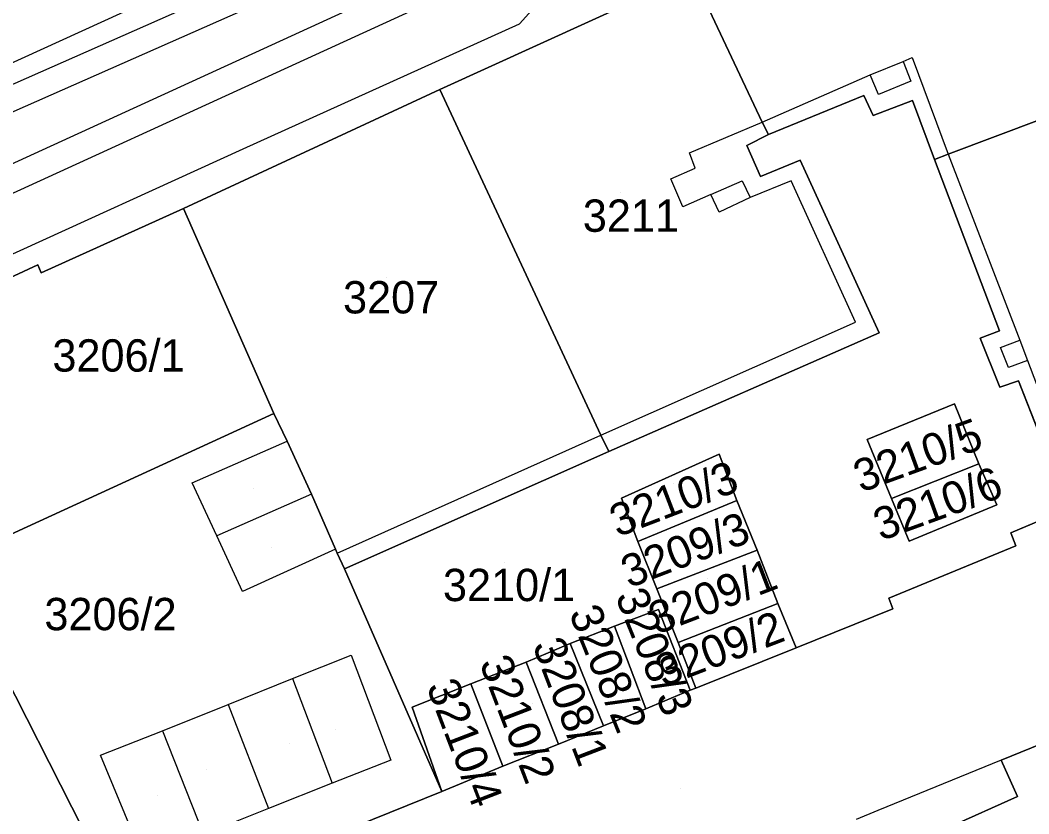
# Model space of a CAD drawing. Extents: x -264070 to -262271, y -1238894 to -1238141.
# Drawn here: x -262975.9 to -262913.5, y -1238614.4 to -1238565.3 of the extents above; entities that cross this region are included whole.
import ezdxf

# ---------------------------------------------------------------- set-up
doc = ezdxf.new("R2010")
doc.units = 0
for name, color, linetype in [('body_kn', 7, 'Continuous'), ('kladpar_druhypozemkov', 7, 'Continuous'), ('kladpar_hranice', 7, 'Continuous'), ('kladpar_parcelnecisla', 7, 'Continuous'), ('kladpar_plochy', 7, 'Continuous'), ('tarchy_linie', 7, 'Continuous'), ('zappar_hrandruhpozemk', 7, 'Continuous')]:
    doc.layers.add(name, color=color, linetype=linetype)

msp = doc.modelspace()

# ---------------------------------------------------------------- linework, layer by layer
at = {"layer": 'body_kn'}
for p, q in [((-262945.02, -1238565.56), (-262945.02, -1238565.56)), ((-262921.28, -1238567.88), (-262921.28, -1238567.88)), ((-262920.72, -1238567.63), (-262920.72, -1238567.63)), ((-262923.32, -1238568.71), (-262923.32, -1238568.71)), ((-262920.8, -1238569.09), (-262920.8, -1238569.09)), ((-262949.95, -1238569.62), (-262949.95, -1238569.62)), ((-262949.95, -1238569.62), (-262949.95, -1238569.62)), ((-262923.72, -1238569.99), (-262923.72, -1238569.99)), ((-262922.8, -1238569.93), (-262922.8, -1238569.93)), ((-262920.71, -1238570.29), (-262920.71, -1238570.29)), ((-262923.14, -1238571.22), (-262923.14, -1238571.22)), ((-262930.01, -1238571.63), (-262930.01, -1238571.63)), ((-262930.01, -1238571.63), (-262930.01, -1238571.63)), ((-262929.61, -1238572.4), (-262929.61, -1238572.4)), ((-262930.96, -1238573.07), (-262930.96, -1238573.07)), ((-262962.12, -1238573.29), (-262962.12, -1238573.29)), ((-262934.51, -1238573.53), (-262934.51, -1238573.53)), ((-262918.49, -1238573.62), (-262918.49, -1238573.62)), ((-262918.49, -1238573.62), (-262918.49, -1238573.62)), ((-262927.65, -1238573.98), (-262927.65, -1238573.98)), ((-262919.34, -1238573.94), (-262919.34, -1238573.94)), ((-262934.14, -1238574.48), (-262934.14, -1238574.48)), ((-262930.1, -1238575), (-262930.1, -1238575)), ((-262935.66, -1238575.14), (-262935.66, -1238575.14)), ((-262931.24, -1238575.26), (-262931.24, -1238575.26)), ((-262928.21, -1238575.26), (-262928.21, -1238575.26)), ((-262933.19, -1238576.11), (-262933.19, -1238576.11)), ((-262933.19, -1238576.11), (-262933.19, -1238576.11)), ((-262930.75, -1238576.3), (-262930.75, -1238576.3)), ((-262934.92, -1238576.88), (-262934.92, -1238576.88)), ((-262965.81, -1238576.98), (-262965.81, -1238576.98)), ((-262965.81, -1238576.98), (-262965.81, -1238576.98)), ((-262932.67, -1238577.2), (-262932.67, -1238577.2)), ((-262974.82, -1238580.47), (-262974.82, -1238580.47)), ((-262974.61, -1238580.95), (-262974.61, -1238580.95)), ((-262924.23, -1238584.02), (-262924.23, -1238584.02)), ((-262922.76, -1238584.67), (-262922.76, -1238584.67)), ((-262922.76, -1238584.67), (-262922.76, -1238584.67)), ((-262916.51, -1238585.01), (-262916.51, -1238585.01)), ((-262915.33, -1238584.55), (-262915.33, -1238584.55)), ((-262915.26, -1238585.58), (-262915.26, -1238585.58)), ((-262914.06, -1238585.13), (-262914.06, -1238585.13)), ((-262914.77, -1238586.81), (-262914.77, -1238586.81)), ((-262913.6, -1238586.38), (-262913.6, -1238586.38)), ((-262915.3, -1238588.03), (-262915.3, -1238588.03)), ((-262914.14, -1238587.63), (-262914.14, -1238587.63)), ((-262918.1, -1238589.06), (-262918.1, -1238589.06)), ((-262960.21, -1238589.66), (-262960.21, -1238589.66)), ((-262960.21, -1238589.66), (-262960.21, -1238589.66)), ((-262939.98, -1238591), (-262939.98, -1238591)), ((-262939.98, -1238591), (-262939.98, -1238591)), ((-262923.52, -1238591.26), (-262923.52, -1238591.26)), ((-262923.52, -1238591.26), (-262923.52, -1238591.26)), ((-262959.39, -1238591.38), (-262959.39, -1238591.38)), ((-262939.5, -1238592.01), (-262939.5, -1238592.01)), ((-262932.66, -1238592.18), (-262932.66, -1238592.18)), ((-262932.66, -1238592.18), (-262932.66, -1238592.18)), ((-262916.61, -1238592.77), (-262916.61, -1238592.77)), ((-262916.61, -1238592.77), (-262916.61, -1238592.77)), ((-262965.26, -1238593.96), (-262965.26, -1238593.96)), ((-262957.89, -1238594.66), (-262957.89, -1238594.66)), ((-262957.89, -1238594.66), (-262957.89, -1238594.66)), ((-262938.71, -1238594.89), (-262938.71, -1238594.89)), ((-262922, -1238594.93), (-262922, -1238594.93)), ((-262931.57, -1238595.05), (-262931.57, -1238595.05)), ((-262931.57, -1238595.05), (-262931.57, -1238595.05)), ((-262915.49, -1238595.31), (-262915.49, -1238595.31)), ((-262963.73, -1238597.23), (-262963.73, -1238597.23)), ((-262914.63, -1238597.04), (-262914.63, -1238597.04)), ((-262956.39, -1238598.05), (-262956.39, -1238598.05)), ((-262956.39, -1238598.05), (-262956.39, -1238598.05)), ((-262937.69, -1238597.59), (-262937.69, -1238597.59)), ((-262930.31, -1238598.12), (-262930.31, -1238598.12)), ((-262930.31, -1238598.12), (-262930.31, -1238598.12)), ((-262920.91, -1238597.57), (-262920.91, -1238597.57)), ((-262914.31, -1238597.85), (-262914.31, -1238597.85)), ((-262914.31, -1238597.85), (-262914.31, -1238597.85)), ((-262956.3, -1238598.3), (-262956.3, -1238598.3)), ((-262956.3, -1238598.3), (-262956.3, -1238598.3)), ((-262955.85, -1238599.27), (-262955.85, -1238599.27)), ((-262936.52, -1238600.51), (-262936.52, -1238600.51)), ((-262962.15, -1238600.68), (-262962.15, -1238600.68)), ((-262922.16, -1238601.09), (-262922.16, -1238601.09)), ((-262936.41, -1238601.79), (-262936.41, -1238601.79)), ((-262936.41, -1238601.79), (-262936.41, -1238601.79)), ((-262929.03, -1238601.42), (-262929.03, -1238601.42)), ((-262929.03, -1238601.42), (-262929.03, -1238601.42)), ((-262921.92, -1238601.75), (-262921.92, -1238601.75)), ((-262939.13, -1238602.82), (-262939.13, -1238602.82)), ((-262939.13, -1238602.82), (-262939.13, -1238602.82)), ((-262941.88, -1238603.9), (-262941.88, -1238603.9)), ((-262941.88, -1238603.9), (-262941.88, -1238603.9)), ((-262935.2, -1238603.84), (-262935.2, -1238603.84)), ((-262927.9, -1238604.16), (-262927.9, -1238604.16)), ((-262955.44, -1238604.61), (-262955.44, -1238604.61)), ((-262944.6, -1238605.04), (-262944.6, -1238605.04)), ((-262944.6, -1238605.04), (-262944.6, -1238605.04)), ((-262959.06, -1238606.05), (-262959.06, -1238606.05)), ((-262948.03, -1238606.38), (-262948.03, -1238606.38)), ((-262948.03, -1238606.38), (-262948.03, -1238606.38)), ((-262934.45, -1238606.78), (-262934.45, -1238606.78)), ((-262934.11, -1238606.66), (-262934.11, -1238606.66)), ((-262963.03, -1238607.66), (-262963.03, -1238607.66)), ((-262951.66, -1238607.83), (-262951.66, -1238607.83)), ((-262937.2, -1238607.94), (-262937.2, -1238607.94)), ((-262967.1, -1238609.3), (-262967.1, -1238609.3)), ((-262967.1, -1238609.3), (-262967.1, -1238609.3)), ((-262939.83, -1238608.98), (-262939.83, -1238608.98)), ((-262942.61, -1238610.11), (-262942.61, -1238610.11)), ((-262970.93, -1238610.8), (-262970.93, -1238610.8)), ((-262970.93, -1238610.8), (-262970.93, -1238610.8)), ((-262952.98, -1238611.11), (-262952.98, -1238611.11)), ((-262915.22, -1238611.11), (-262915.22, -1238611.11)), ((-262915.22, -1238611.11), (-262915.22, -1238611.11)), ((-262946.04, -1238611.48), (-262946.04, -1238611.48)), ((-262956.61, -1238612.54), (-262956.61, -1238612.54)), ((-262949.83, -1238613.04), (-262949.83, -1238613.04)), ((-262914.21, -1238613.35), (-262914.21, -1238613.35)), ((-262960.55, -1238614.11), (-262960.55, -1238614.11)), ((-262922.85, -1238614.23), (-262922.85, -1238614.23))]:
    msp.add_line(p, q, dxfattribs=at)
at = {"layer": 'kladpar_druhypozemkov'}
for p, q in [((-262938.75, -1238575.99), (-262938.75, -1238575.99)), ((-262953.25, -1238581.27), (-262953.25, -1238581.27)), ((-262969.85, -1238584.87), (-262969.85, -1238584.87)), ((-262919.89, -1238590.99), (-262919.89, -1238590.99)), ((-262961.5, -1238594.32), (-262961.5, -1238594.32)), ((-262935.5, -1238594), (-262935.5, -1238594)), ((-262917.98, -1238594.35), (-262917.98, -1238594.35)), ((-262934.37, -1238596.81), (-262934.37, -1238596.81)), ((-262960.38, -1238597.95), (-262960.38, -1238597.95)), ((-262945.93, -1238598.9), (-262945.93, -1238598.9)), ((-262933.38, -1238599.87), (-262933.38, -1238599.87)), ((-262932.19, -1238603.23), (-262932.19, -1238603.23)), ((-262936.09, -1238604.27), (-262936.09, -1238604.27)), ((-262938.71, -1238605.41), (-262938.71, -1238605.41)), ((-262941.47, -1238606.59), (-262941.47, -1238606.59)), ((-262944.19, -1238607.63), (-262944.19, -1238607.63)), ((-262956.38, -1238609.2), (-262956.38, -1238609.2)), ((-262947.65, -1238608.96), (-262947.65, -1238608.96)), ((-262959.25, -1238610.07), (-262959.25, -1238610.07)), ((-262964.38, -1238611.7), (-262964.38, -1238611.7)), ((-262935.05, -1238612.86), (-262935.05, -1238612.86)), ((-262967.38, -1238613.32), (-262967.38, -1238613.32))]:
    msp.add_line(p, q, dxfattribs=at)
at = {"layer": 'kladpar_hranice'}
for points in [[(-262922.36, -1238556.98), (-262922.53, -1238556.54), (-262919.09, -1238555.05), (-262918.93, -1238555.38), (-262913.35, -1238552.78), (-262907.03, -1238569.3), (-262918.49, -1238573.62), (-262919.34, -1238573.94), (-262920.71, -1238570.29), (-262923.14, -1238571.22), (-262923.72, -1238569.99), (-262929.61, -1238572.4), (-262930.01, -1238571.63), (-262934.31, -1238562.47), (-262922.36, -1238556.98)], [(-262934.31, -1238562.47), (-262949.95, -1238569.62), (-262965.81, -1238576.98), (-262974.61, -1238580.95), (-262974.82, -1238580.47), (-262978.33, -1238582.09), (-262978.13, -1238582.53), (-262983.58, -1238584.94), (-262986.93, -1238586.37), (-262986.63, -1238586.99), (-263016.81, -1238600.45), (-263020.21, -1238602), (-263050.35, -1238615.68)], [(-262934.31, -1238562.47), (-262930.01, -1238571.63), (-262929.61, -1238572.4), (-262930.96, -1238573.07), (-262930.1, -1238575), (-262927.65, -1238573.98), (-262922.76, -1238584.67), (-262939.5, -1238592.01), (-262939.98, -1238591), (-262949.95, -1238569.62), (-262934.31, -1238562.47)], [(-262907.03, -1238569.3), (-262903.45, -1238578.5), (-262903.13, -1238578.4), (-262902.03, -1238581.41), (-262902.23, -1238581.48), (-262898.81, -1238590.44), (-262909.37, -1238594.9), (-262910.23, -1238595.25), (-262911.06, -1238595.54), (-262914.14, -1238587.63), (-262915.3, -1238588.03), (-262916.51, -1238585.01), (-262915.33, -1238584.55), (-262919.34, -1238573.94), (-262918.49, -1238573.62), (-262907.03, -1238569.3)], [(-262949.95, -1238569.62), (-262939.98, -1238591), (-262939.5, -1238592.01), (-262955.85, -1238599.27), (-262956.3, -1238598.3), (-262956.39, -1238598.05), (-262957.89, -1238594.66), (-262959.39, -1238591.38), (-262960.21, -1238589.66), (-262965.81, -1238576.98), (-262949.95, -1238569.62)], [(-262922.76, -1238584.67), (-262927.65, -1238573.98), (-262930.1, -1238575), (-262930.96, -1238573.07), (-262929.61, -1238572.4), (-262923.72, -1238569.99), (-262923.14, -1238571.22), (-262920.71, -1238570.29), (-262919.34, -1238573.94), (-262915.33, -1238584.55), (-262916.51, -1238585.01), (-262915.3, -1238588.03), (-262914.14, -1238587.63), (-262911.06, -1238595.54), (-262914.63, -1238597.04)], [(-262965.81, -1238576.98), (-262960.21, -1238589.66), (-262976.99, -1238597.37), (-262980.41, -1238598.9), (-262986.63, -1238586.99), (-262986.93, -1238586.37), (-262983.58, -1238584.94), (-262978.13, -1238582.53), (-262978.33, -1238582.09), (-262974.82, -1238580.47), (-262974.61, -1238580.95), (-262965.81, -1238576.98)], [(-262914.63, -1238597.04), (-262914.31, -1238597.85), (-262922.16, -1238601.09), (-262921.92, -1238601.75), (-262927.9, -1238604.16), (-262929.03, -1238601.42), (-262930.31, -1238598.12), (-262931.57, -1238595.05), (-262932.66, -1238592.18), (-262938.71, -1238594.89), (-262937.69, -1238597.59), (-262936.52, -1238600.51), (-262935.2, -1238603.84), (-262934.11, -1238606.66), (-262934.45, -1238606.78), (-262936.41, -1238601.79), (-262939.13, -1238602.82), (-262941.88, -1238603.9), (-262944.6, -1238605.04), (-262948.03, -1238606.38), (-262951.66, -1238607.83), (-262949.83, -1238613.04), (-262955.85, -1238599.27), (-262939.5, -1238592.01), (-262922.76, -1238584.67)], [(-263050.35, -1238615.68), (-263020.21, -1238602), (-263016.81, -1238600.45), (-262986.63, -1238586.99), (-262980.41, -1238598.9), (-262969.23, -1238620.88)], [(-262923.52, -1238591.26), (-262918.1, -1238589.06), (-262916.61, -1238592.77), (-262922, -1238594.93), (-262923.52, -1238591.26)], [(-262915.49, -1238595.31), (-262916.61, -1238592.77), (-262918.1, -1238589.06), (-262923.52, -1238591.26), (-262922, -1238594.93), (-262920.91, -1238597.57), (-262915.49, -1238595.31)], [(-262960.21, -1238589.66), (-262959.39, -1238591.38), (-262957.89, -1238594.66), (-262956.39, -1238598.05), (-262956.3, -1238598.3), (-262955.85, -1238599.27), (-262949.83, -1238613.04), (-262969.23, -1238620.88), (-262980.41, -1238598.9), (-262976.99, -1238597.37), (-262960.21, -1238589.66)], [(-262932.66, -1238592.18), (-262931.57, -1238595.05), (-262937.69, -1238597.59), (-262938.71, -1238594.89), (-262932.66, -1238592.18)], [(-262916.61, -1238592.77), (-262915.49, -1238595.31), (-262920.91, -1238597.57), (-262922, -1238594.93), (-262916.61, -1238592.77)], [(-262931.57, -1238595.05), (-262930.31, -1238598.12), (-262936.52, -1238600.51), (-262937.69, -1238597.59), (-262931.57, -1238595.05)], [(-262914.31, -1238597.85), (-262914.63, -1238597.04), (-262911.06, -1238595.54)], [(-262969.23, -1238620.88), (-262949.83, -1238613.04), (-262946.04, -1238611.48), (-262942.61, -1238610.11), (-262939.83, -1238608.98), (-262937.2, -1238607.94), (-262934.45, -1238606.78), (-262934.11, -1238606.66), (-262927.9, -1238604.16), (-262921.92, -1238601.75), (-262922.16, -1238601.09), (-262914.31, -1238597.85)], [(-262930.31, -1238598.12), (-262929.03, -1238601.42), (-262935.2, -1238603.84), (-262936.52, -1238600.51), (-262930.31, -1238598.12)], [(-262936.41, -1238601.79), (-262934.45, -1238606.78), (-262937.2, -1238607.94), (-262939.13, -1238602.82), (-262936.41, -1238601.79)], [(-262929.03, -1238601.42), (-262927.9, -1238604.16), (-262934.11, -1238606.66), (-262935.2, -1238603.84), (-262929.03, -1238601.42)], [(-262939.13, -1238602.82), (-262937.2, -1238607.94), (-262939.83, -1238608.98), (-262941.88, -1238603.9), (-262939.13, -1238602.82)], [(-262941.88, -1238603.9), (-262939.83, -1238608.98), (-262942.61, -1238610.11), (-262944.6, -1238605.04), (-262941.88, -1238603.9)], [(-262944.6, -1238605.04), (-262942.61, -1238610.11), (-262946.04, -1238611.48), (-262948.03, -1238606.38), (-262944.6, -1238605.04)], [(-262948.03, -1238606.38), (-262946.04, -1238611.48), (-262949.83, -1238613.04), (-262951.66, -1238607.83), (-262948.03, -1238606.38)], [(-262918.44, -1238615.25), (-262914.21, -1238613.35), (-262915.22, -1238611.11), (-262904.63, -1238606.79)], [(-262904.63, -1238606.79), (-262915.22, -1238611.11), (-262914.21, -1238613.35), (-262918.44, -1238615.25)]]:
    msp.add_lwpolyline(points, dxfattribs=at)
at = {"layer": 'kladpar_plochy'}
for p, q in [((-262929.61, -1238572.4), (-262923.72, -1238569.99)), ((-262923.72, -1238569.99), (-262923.14, -1238571.22)), ((-262923.14, -1238571.22), (-262920.71, -1238570.29)), ((-262920.71, -1238570.29), (-262919.34, -1238573.94)), ((-262930.96, -1238573.07), (-262929.61, -1238572.4)), ((-262930.1, -1238575), (-262930.96, -1238573.07)), ((-262927.65, -1238573.98), (-262930.1, -1238575)), ((-262922.76, -1238584.67), (-262927.65, -1238573.98)), ((-262919.34, -1238573.94), (-262915.33, -1238584.55)), ((-262939.5, -1238592.01), (-262922.76, -1238584.67)), ((-262915.33, -1238584.55), (-262916.51, -1238585.01)), ((-262916.51, -1238585.01), (-262915.3, -1238588.03)), ((-262915.3, -1238588.03), (-262914.14, -1238587.63)), ((-262914.14, -1238587.63), (-262911.06, -1238595.54)), ((-262918.1, -1238589.06), (-262923.52, -1238591.26)), ((-262916.61, -1238592.77), (-262918.1, -1238589.06)), ((-262923.52, -1238591.26), (-262922, -1238594.93)), ((-262955.85, -1238599.27), (-262939.5, -1238592.01)), ((-262932.66, -1238592.18), (-262938.71, -1238594.89)), ((-262931.57, -1238595.05), (-262932.66, -1238592.18)), ((-262915.49, -1238595.31), (-262916.61, -1238592.77)), ((-262938.71, -1238594.89), (-262937.69, -1238597.59)), ((-262922, -1238594.93), (-262920.91, -1238597.57)), ((-262930.31, -1238598.12), (-262931.57, -1238595.05)), ((-262920.91, -1238597.57), (-262915.49, -1238595.31)), ((-262911.06, -1238595.54), (-262914.63, -1238597.04)), ((-262914.63, -1238597.04), (-262914.31, -1238597.85)), ((-262937.69, -1238597.59), (-262936.52, -1238600.51)), ((-262929.03, -1238601.42), (-262930.31, -1238598.12)), ((-262914.31, -1238597.85), (-262922.16, -1238601.09)), ((-262949.83, -1238613.04), (-262955.85, -1238599.27)), ((-262936.52, -1238600.51), (-262935.2, -1238603.84)), ((-262922.16, -1238601.09), (-262921.92, -1238601.75)), ((-262936.41, -1238601.79), (-262939.13, -1238602.82)), ((-262934.45, -1238606.78), (-262936.41, -1238601.79)), ((-262927.9, -1238604.16), (-262929.03, -1238601.42)), ((-262921.92, -1238601.75), (-262927.9, -1238604.16)), ((-262939.13, -1238602.82), (-262941.88, -1238603.9)), ((-262941.88, -1238603.9), (-262944.6, -1238605.04)), ((-262935.2, -1238603.84), (-262934.11, -1238606.66)), ((-262944.6, -1238605.04), (-262948.03, -1238606.38)), ((-262948.03, -1238606.38), (-262951.66, -1238607.83)), ((-262934.11, -1238606.66), (-262934.45, -1238606.78)), ((-262951.66, -1238607.83), (-262949.83, -1238613.04))]:
    msp.add_line(p, q, dxfattribs=at)
for points in [[(-262922.36, -1238556.98), (-262922.53, -1238556.54), (-262919.09, -1238555.05), (-262918.93, -1238555.38), (-262913.35, -1238552.78), (-262907.03, -1238569.3), (-262918.49, -1238573.62), (-262919.34, -1238573.94), (-262920.71, -1238570.29), (-262923.14, -1238571.22), (-262923.72, -1238569.99), (-262929.61, -1238572.4), (-262930.01, -1238571.63), (-262934.31, -1238562.47)], [(-262934.31, -1238562.47), (-262930.01, -1238571.63), (-262929.61, -1238572.4), (-262930.96, -1238573.07), (-262930.1, -1238575), (-262927.65, -1238573.98), (-262922.76, -1238584.67), (-262939.5, -1238592.01), (-262939.98, -1238591), (-262949.95, -1238569.62)], [(-262907.03, -1238569.3), (-262903.45, -1238578.5), (-262903.13, -1238578.4), (-262902.03, -1238581.41), (-262902.23, -1238581.48), (-262898.81, -1238590.44), (-262909.37, -1238594.9), (-262910.23, -1238595.25), (-262911.06, -1238595.54), (-262914.14, -1238587.63), (-262915.3, -1238588.03), (-262916.51, -1238585.01), (-262915.33, -1238584.55), (-262919.34, -1238573.94), (-262918.49, -1238573.62)], [(-262949.95, -1238569.62), (-262939.98, -1238591), (-262939.5, -1238592.01), (-262955.85, -1238599.27), (-262956.3, -1238598.3), (-262956.39, -1238598.05), (-262957.89, -1238594.66), (-262959.39, -1238591.38), (-262960.21, -1238589.66), (-262965.81, -1238576.98)], [(-262965.81, -1238576.98), (-262960.21, -1238589.66), (-262976.99, -1238597.37), (-262980.41, -1238598.9), (-262986.63, -1238586.99), (-262986.93, -1238586.37), (-262983.58, -1238584.94), (-262978.13, -1238582.53), (-262978.33, -1238582.09), (-262974.82, -1238580.47), (-262974.61, -1238580.95)], [(-262923.52, -1238591.26), (-262918.1, -1238589.06), (-262916.61, -1238592.77), (-262922, -1238594.93)], [(-262960.21, -1238589.66), (-262959.39, -1238591.38), (-262957.89, -1238594.66), (-262956.39, -1238598.05), (-262956.3, -1238598.3), (-262955.85, -1238599.27), (-262949.83, -1238613.04), (-262969.23, -1238620.88), (-262980.41, -1238598.9), (-262976.99, -1238597.37)], [(-262932.66, -1238592.18), (-262931.57, -1238595.05), (-262937.69, -1238597.59), (-262938.71, -1238594.89)], [(-262916.61, -1238592.77), (-262915.49, -1238595.31), (-262920.91, -1238597.57), (-262922, -1238594.93)], [(-262931.57, -1238595.05), (-262930.31, -1238598.12), (-262936.52, -1238600.51), (-262937.69, -1238597.59)], [(-262930.31, -1238598.12), (-262929.03, -1238601.42), (-262935.2, -1238603.84), (-262936.52, -1238600.51)], [(-262936.41, -1238601.79), (-262934.45, -1238606.78), (-262937.2, -1238607.94), (-262939.13, -1238602.82)], [(-262929.03, -1238601.42), (-262927.9, -1238604.16), (-262934.11, -1238606.66), (-262935.2, -1238603.84)], [(-262939.13, -1238602.82), (-262937.2, -1238607.94), (-262939.83, -1238608.98), (-262941.88, -1238603.9)], [(-262941.88, -1238603.9), (-262939.83, -1238608.98), (-262942.61, -1238610.11), (-262944.6, -1238605.04)], [(-262944.6, -1238605.04), (-262942.61, -1238610.11), (-262946.04, -1238611.48), (-262948.03, -1238606.38)], [(-262948.03, -1238606.38), (-262946.04, -1238611.48), (-262949.83, -1238613.04), (-262951.66, -1238607.83)]]:
    msp.add_lwpolyline(points, close=True, dxfattribs=at)
for points in [[(-262934.31, -1238562.47), (-262949.95, -1238569.62), (-262965.81, -1238576.98), (-262974.61, -1238580.95), (-262974.82, -1238580.47), (-262978.33, -1238582.09), (-262978.13, -1238582.53), (-262983.58, -1238584.94), (-262986.93, -1238586.37), (-262986.63, -1238586.99), (-263016.81, -1238600.45), (-263020.21, -1238602), (-263050.35, -1238615.68)], [(-263050.35, -1238615.68), (-263020.21, -1238602), (-263016.81, -1238600.45), (-262986.63, -1238586.99), (-262980.41, -1238598.9), (-262969.23, -1238620.88)], [(-262969.23, -1238620.88), (-262949.83, -1238613.04), (-262946.04, -1238611.48), (-262942.61, -1238610.11), (-262939.83, -1238608.98), (-262937.2, -1238607.94), (-262934.45, -1238606.78), (-262934.11, -1238606.66), (-262927.9, -1238604.16), (-262921.92, -1238601.75), (-262922.16, -1238601.09), (-262914.31, -1238597.85), (-262914.63, -1238597.04), (-262911.06, -1238595.54)], [(-262918.44, -1238615.25), (-262914.21, -1238613.35), (-262915.22, -1238611.11), (-262904.63, -1238606.79)], [(-262904.63, -1238606.79), (-262915.22, -1238611.11), (-262914.21, -1238613.35), (-262918.44, -1238615.25)]]:
    msp.add_lwpolyline(points, dxfattribs=at)
at = {"layer": 'tarchy_linie'}
for points in [[(-263127.28, -1238639.92), (-263086.66, -1238619.65), (-263043.33, -1238598.79), (-262997.67, -1238578.69), (-262948.78, -1238557.1), (-262916.97, -1238543.57), (-262916.75, -1238544.13), (-262916.4, -1238545.02), (-262915.51, -1238547.31), (-262914.89, -1238548.89), (-262945.47, -1238561.89), (-262992.44, -1238583.4), (-263039.43, -1238605.06), (-263086.63, -1238626.71), (-263123.25, -1238643.79), (-263125.06, -1238644.64), (-263125.78, -1238643.09), (-263126.6, -1238641.32), (-263127.07, -1238640.31), (-263127.28, -1238639.92)], [(-263126.6, -1238641.32), (-263085.98, -1238621.04), (-263042.68, -1238600.2), (-262997.04, -1238580.11), (-262948.16, -1238558.52), (-262916.4, -1238545.02)], [(-263123.97, -1238642.25), (-263087.34, -1238625.17), (-263040.14, -1238603.52), (-262993.15, -1238581.86), (-262946.16, -1238560.33), (-262915.51, -1238547.31)]]:
    msp.add_lwpolyline(points, dxfattribs=at)
at = {"layer": 'zappar_hrandruhpozemk'}
for p, q in [((-262962.12, -1238573.29), (-262945.02, -1238565.56)), ((-263007.66, -1238594.03), (-262962.12, -1238573.29)), ((-262934.92, -1238576.88), (-262935.66, -1238575.14)), ((-262933.19, -1238576.11), (-262931.24, -1238575.26)), ((-262931.24, -1238575.26), (-262930.75, -1238576.3)), ((-262939.98, -1238591), (-262924.23, -1238584.02)), ((-262913.6, -1238586.38), (-262910.23, -1238595.25)), ((-262956.3, -1238598.3), (-262939.98, -1238591)), ((-262965.26, -1238593.96), (-262959.39, -1238591.38)), ((-262957.89, -1238594.66), (-262963.73, -1238597.23)), ((-262956.39, -1238598.05), (-262962.15, -1238600.68)), ((-262963.03, -1238607.66), (-262959.06, -1238606.05)), ((-262959.06, -1238606.05), (-262956.61, -1238612.54)), ((-262963.03, -1238607.66), (-262960.55, -1238614.11)), ((-262967.1, -1238609.3), (-262964.57, -1238615.71))]:
    msp.add_line(p, q, dxfattribs=at)
for points in [[(-263000.02, -1238578.86), (-262980.78, -1238569.95), (-262949.77, -1238555.79)], [(-262945.02, -1238565.56), (-262942.77, -1238563.03), (-262941.11, -1238561.97)], [(-262930.01, -1238571.63), (-262923.32, -1238568.71), (-262921.28, -1238567.88)], [(-262921.28, -1238567.88), (-262920.8, -1238569.09), (-262922.8, -1238569.93), (-262923.32, -1238568.71)], [(-262921.28, -1238567.88), (-262920.72, -1238567.63), (-262918.49, -1238573.62)], [(-262935.66, -1238575.14), (-262934.14, -1238574.48), (-262934.51, -1238573.53), (-262930.01, -1238571.63)], [(-262918.49, -1238573.62), (-262914.06, -1238585.13), (-262913.6, -1238586.38)], [(-262924.23, -1238584.02), (-262928.21, -1238575.26), (-262930.75, -1238576.3), (-262932.67, -1238577.2), (-262933.19, -1238576.11), (-262934.92, -1238576.88)], [(-262913.6, -1238586.38), (-262914.77, -1238586.81), (-262915.26, -1238585.58), (-262914.06, -1238585.13)], [(-262962.15, -1238600.68), (-262963.73, -1238597.23), (-262965.26, -1238593.96)], [(-262959.06, -1238606.05), (-262955.44, -1238604.61), (-262952.98, -1238611.11), (-262956.61, -1238612.54), (-262960.55, -1238614.11), (-262964.57, -1238615.71), (-262968.28, -1238617.22), (-262970.93, -1238610.8)], [(-262970.93, -1238610.8), (-262967.1, -1238609.3), (-262963.03, -1238607.66)], [(-262915.22, -1238611.11), (-262922.85, -1238614.23), (-262924.19, -1238614.78)]]:
    msp.add_lwpolyline(points, dxfattribs=at)

# ---------------------------------------------------------------- texts
at = {"layer": 'kladpar_parcelnecisla'}
for s, p in [('3211', (-262941.1, -1238578.42)), ('3207', (-262955.933, -1238583.47)), ('3206/1', (-262973.911, -1238587.07)), ('3210/1', (-262949.752, -1238601.27)), ('3206/2', (-262974.407, -1238603.07))]:
    msp.add_text(s, height=2, dxfattribs=at).set_placement(p)
for s, rotation, p in [('3210/5', 20, (-262923.89, -1238594.573)), ('3210/3', 21, (-262938.949, -1238597.331)), ('3210/6', 20, (-262922.658, -1238597.564)), ('3209/3', 21, (-262938.241, -1238600.487)), ('3209/1', 21, (-262936.533, -1238603.364)), ('3208/3', 292, (-262939.117, -1238600.959)), ('3208/2', 292, (-262941.981, -1238602.004)), ('3209/2', 21, (-262936.106, -1238606.612)), ('3208/1', 291, (-262944.235, -1238603.998)), ('3210/2', 291, (-262947.515, -1238605.086)), ('3210/4', 291, (-262950.794, -1238606.547))]:
    msp.add_text(s, height=2, rotation=rotation, dxfattribs=at).set_placement(p)

doc.saveas('drawing.dxf')
